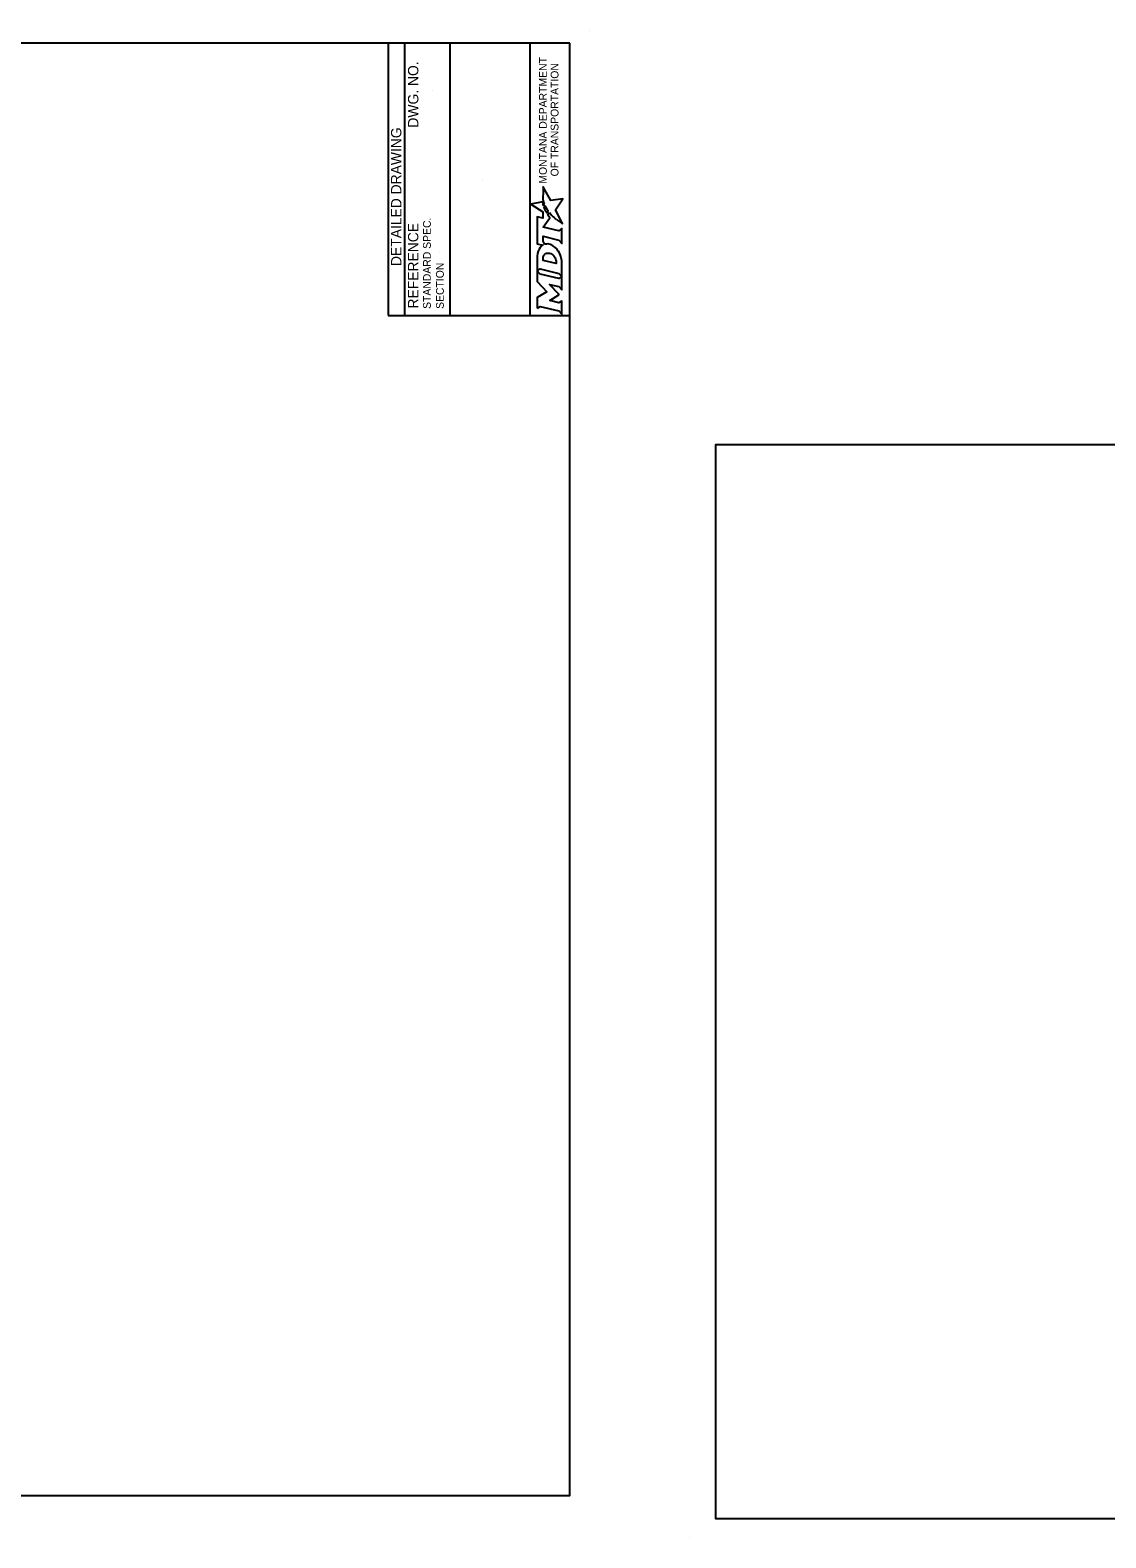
# Model space of a CAD drawing. Extents: x 49991.4 to 50021, y 49987.6 to 50011.4.
# Drawn here: x 50004.46 to 50012.75, y 49999.74 to 50011.36 of the extents above; entities that cross this region are included whole.
import ezdxf

# ---------------------------------------------------------------- set-up
doc = ezdxf.new("R2010")
doc.units = 0
doc.layers.add('Level 1', color=7, linetype='Continuous')
doc.layers.add('Level 3', color=7, linetype='Continuous')

msp = doc.modelspace()

# ---------------------------------------------------------------- linework, layer by layer
at = {"layer": 'Level 1'}
for p, q in [((50008.765, 50011.363), (50008.765, 50011.363)), ((50009.537, 49999.736), (50009.537, 49999.736))]:
    msp.add_line(p, q, dxfattribs=at)
for points in [[(50008.615, 50011.263), (50000.336, 50011.263), (50000.336, 50000.062), (50008.615, 50000.062)], [(50020.938, 50008.165), (50009.737, 50008.165), (50009.737, 49999.886), (50020.938, 49999.886)]]:
    msp.add_lwpolyline(points, close=True, dxfattribs=at)
at = {"layer": 'Level 3'}
for p, q in [((50007.215, 50011.263), (50007.215, 50009.163)), ((50007.34, 50011.263), (50007.34, 50009.163)), ((50007.69, 50011.263), (50007.69, 50009.163)), ((50008.308, 50011.263), (50008.308, 50009.163)), ((50007.555, 50010.899), (50007.555, 50010.899)), ((50007.939, 50010.213), (50007.939, 50010.213)), ((50007.614, 50009.657), (50007.614, 50009.657)), ((50007.215, 50009.163), (50008.615, 50009.163))]:
    msp.add_line(p, q, dxfattribs=at)
for points in [[(50008.514, 50009.9), (50008.538, 50009.885), (50008.546, 50009.88), (50008.554, 50009.875), (50008.559, 50009.872), (50008.505, 50009.978), (50008.561, 50010.061), (50008.468, 50010.048), (50008.409, 50010.155), (50008.409, 50010.106), (50008.408, 50010.076), (50008.408, 50010.055), (50008.409, 50010.048), (50008.411, 50010.043), (50008.413, 50010.035), (50008.417, 50010.025)], [(50008.417, 50010.025), (50008.411, 50010.014), (50008.409, 50010.026), (50008.407, 50010.038), (50008.316, 50010.02), (50008.408, 50009.961), (50008.408, 50009.914), (50008.364, 50009.924), (50008.364, 50009.715), (50008.407, 50009.705), (50008.398, 50009.699)], [(50008.445, 50009.974), (50008.446, 50009.972), (50008.437, 50009.954), (50008.431, 50009.964), (50008.429, 50009.968), (50008.425, 50009.977), (50008.422, 50009.982), (50008.419, 50009.99), (50008.416, 50009.998), (50008.424, 50010.009), (50008.426, 50010.005), (50008.428, 50010.001), (50008.431, 50009.997), (50008.434, 50009.992), (50008.435, 50009.99), (50008.436, 50009.987), (50008.438, 50009.985), (50008.439, 50009.982), (50008.441, 50009.98), (50008.443, 50009.977), (50008.445, 50009.974)], [(50008.423, 50009.711), (50008.41, 50009.736), (50008.41, 50009.773), (50008.531, 50009.744), (50008.553, 50009.717), (50008.553, 50009.833), (50008.531, 50009.816), (50008.41, 50009.844), (50008.462, 50009.915), (50008.447, 50009.937), (50008.458, 50009.956)], [(50008.498, 50009.914), (50008.498, 50009.914)], [(50008.451, 50009.644), (50008.459, 50009.643), (50008.468, 50009.64), (50008.476, 50009.635), (50008.484, 50009.63), (50008.491, 50009.623), (50008.497, 50009.615), (50008.502, 50009.607), (50008.506, 50009.598), (50008.508, 50009.589), (50008.509, 50009.58), (50008.509, 50009.564), (50008.409, 50009.587), (50008.409, 50009.603), (50008.41, 50009.611), (50008.412, 50009.619), (50008.415, 50009.625), (50008.419, 50009.631), (50008.424, 50009.636), (50008.43, 50009.64), (50008.436, 50009.642), (50008.443, 50009.644), (50008.446, 50009.644), (50008.451, 50009.644)], [(50008.546, 50009.618), (50008.543, 50009.626), (50008.538, 50009.639), (50008.527, 50009.66)], [(50008.364, 50009.62), (50008.364, 50009.506), (50008.387, 50009.521), (50008.531, 50009.487), (50008.553, 50009.462), (50008.553, 50009.572)], [(50008.387, 50009.481), (50008.364, 50009.506), (50008.364, 50009.424), (50008.437, 50009.344), (50008.364, 50009.3), (50008.364, 50009.218)], [(50008.364, 50009.218), (50008.388, 50009.232), (50008.531, 50009.198), (50008.553, 50009.173), (50008.553, 50009.274), (50008.531, 50009.261), (50008.461, 50009.277), (50008.53, 50009.321), (50008.53, 50009.326), (50008.46, 50009.401), (50008.531, 50009.385), (50008.553, 50009.36), (50008.553, 50009.462), (50008.53, 50009.448), (50008.387, 50009.481)]]:
    msp.add_lwpolyline(points, dxfattribs=at)
for centre, radius, start, end in [((50008.443, 50009.643), 0.0709, 69.5329, 105.8582), ((50008.425, 50009.599), 0.118, 30.9103, 69.1383)]:
    msp.add_arc(centre, radius, start, end, dxfattribs=at)
for centre, major_axis, ratio, start_param, end_param in [((50008.468, 50009.945), (0.0097, -0.0112), 0.021651, 3.157348, 6.283185), ((50008.487, 50009.924), (0.0102, -0.0098), 0.016458, 3.141593, 6.279097), ((50008.506, 50009.907), (0.00806, -0.00694), 0.008222, 0, 3.137361), ((50008.412, 50009.618), (0.0037, 0.0834), 0.568097, 0.61298, 1.570796), ((50008.404, 50009.673), (0.0295, 0.0361), 0.469099, 1.225588, 1.570796), ((50008.405, 50009.573), (-0.148, 0), 0.987302, 3.139398, 3.456847)]:
    msp.add_ellipse(centre, major_axis=major_axis, ratio=ratio, start_param=start_param, end_param=end_param, dxfattribs=at)

# ---------------------------------------------------------------- texts
for s, height, p in [('MONTANA DEPARTMENT', 0.06, (50008.438, 50010.179)), ('DWG. NO.', 0.08, (50007.448, 50010.611)), ('OF TRANSPORTATION', 0.06, (50008.528, 50010.235)), ('DETAILED DRAWING', 0.0799, (50007.317, 50009.544)), ('REFERENCE', 0.08, (50007.448, 50009.216)), ('STANDARD SPEC.', 0.06, (50007.544, 50009.213)), ('SECTION', 0.06, (50007.644, 50009.213))]:
    msp.add_text(s, height=height, rotation=90, dxfattribs=at).set_placement(p)

doc.saveas('drawing.dxf')
